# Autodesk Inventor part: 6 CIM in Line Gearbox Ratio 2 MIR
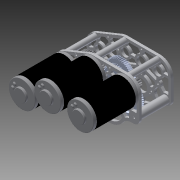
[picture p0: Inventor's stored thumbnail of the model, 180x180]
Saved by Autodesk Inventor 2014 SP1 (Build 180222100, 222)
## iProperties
Created: 2014-11
Part Number: 6 CIM in Line Gearbox Ratio 2 MIR
Material: Generic
Document SubType Name: Modeling
Designer: Michael
Density: 1 g/cm^3
Appearance: Default
Author: Michael
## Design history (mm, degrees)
derived "6 CIM in Line Gearbox Ratio 2.iam"
body "Solid1"
node "Gearbox Plate Ratio 2.ipt:1"
node "40T .5 inch.ipt:1"
node "11t.ipt:1"
node "11t.ipt:2"
node "50t.ipt:1"
node "11t.ipt:3"
node "36t.ipt:1"
node "217-2000 CIM motor.ipt:1"
node "217-2000 CIM motor.ipt:2"
node "217-2000 CIM motor.ipt:3"
node "User Library-16T Gear AndyMark am-0747.ipt:1"
node "40tDogGear.ipt:1"
node "60tDogGear.ipt:1"
node "Piston Mount in Line.ipt:1"
node "Gearbox Plate Ratio 2 MIR.ipt:1"
node "Standoff.ipt:1"
node "Big Standoff.ipt:1"
node "Standoff.ipt:2"
node "Standoff.ipt:3"
node "Big Standoff.ipt:2"
